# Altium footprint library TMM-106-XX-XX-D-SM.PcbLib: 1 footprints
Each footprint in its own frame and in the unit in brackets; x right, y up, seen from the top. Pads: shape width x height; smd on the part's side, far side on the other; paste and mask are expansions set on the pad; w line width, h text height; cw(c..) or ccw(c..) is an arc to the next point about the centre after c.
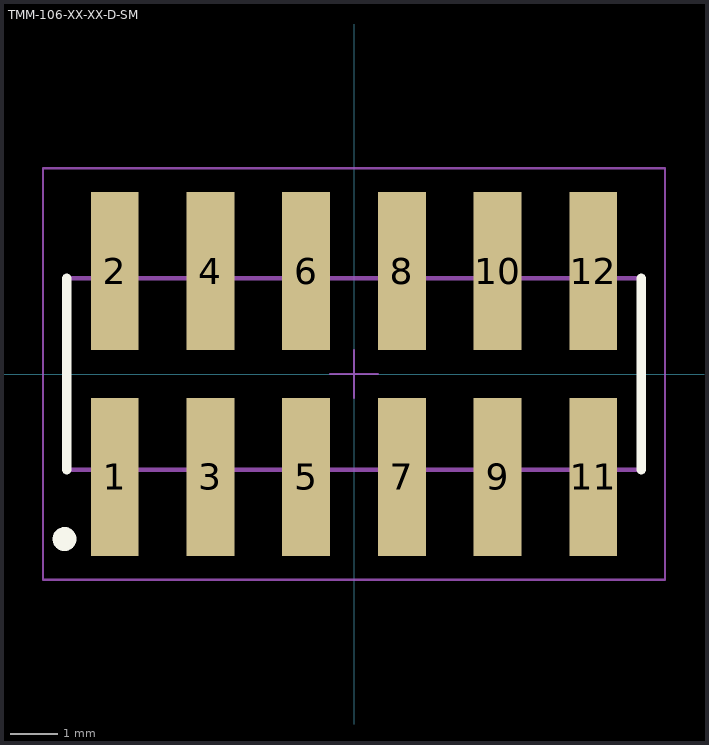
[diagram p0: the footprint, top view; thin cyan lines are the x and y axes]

## TMM-106-XX-XX-D-SM [mm] "2.00mm pitch, 12 pin, terminal strip; double row, SMT"
height 2.77
pads (12):
  rect 1x3.3 smd mask+0: 1(-5,-2.15) 2(-5,2.15) 3(-3,-2.15) 4(-3,2.15) 5(-1,-2.15) 6(-1,2.15) 7(1,-2.15) 8(1,2.15) 9(3,-2.15) 10(3,2.15) 11(5,-2.15) 12(5,2.15)
Top Overlay:
  circle w0.25: c-6.05,-3.45 r0.125
  lines w0.2: -6,-2 -6,2 ; 6,-2 6,2
Mechanical 12:
  lines w0.001: -6,-2 6,-2 6,2 -6,2 -6,-2
Mechanical 13:
  lines w0.1: -6,-2 6,-2 6,2 -6,2 -6,-2
  text ".Designator" at 0,-0.127 h1.52
Mechanical 15:
  lines w0.05: -0.5,0 0.5,0 ; 0,-0.5 0,0.5 ; -6.5,-4.3 6.5,-4.3 6.5,4.3 -6.5,4.3 -6.5,-4.3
